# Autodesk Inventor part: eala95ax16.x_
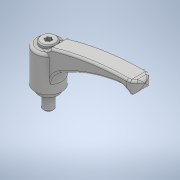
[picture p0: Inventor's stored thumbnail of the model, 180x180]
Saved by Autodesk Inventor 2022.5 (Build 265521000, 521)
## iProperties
Created: 2018-05
Part Number: eala95ax16.x_
Material: 一般
Document SubType Name: Modeling
Designer: imaocorp
Density: 1 g/cm^3
Appearance: 既定
Sending System: SOLIDWORKS 2016-2016286
MC: AMD64
MC_MODEL: AMD64 Family 21 Model 2 Stepping 0, AuthenticAMD
OS: Windows_NT
FRU: Parasolid Version 28.0, build 224,  7-29-2016
FORMAT: text
GUISE: transmit
KEY: eala95ax16
FILE: eala95ax16.x_t
DATE: Fri May 18 11:32:49 2018
Author: imaocorp
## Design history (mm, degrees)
feature "Base1"
node "ソリッド1"
